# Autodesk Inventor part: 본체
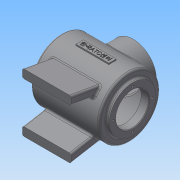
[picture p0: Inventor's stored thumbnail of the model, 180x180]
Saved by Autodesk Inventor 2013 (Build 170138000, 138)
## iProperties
Created: 2015-01
Part Number: 본체
Material: 일반
Document SubType Name: Modeling
Designer: Administrator
Density: 1 g/cm^3
Mass: 376.8 g
Surface Area: 1060.37 cm^2
Volume: 376.8 cm^3
Author: Administrator
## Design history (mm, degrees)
sketch "스케치1"
  geometry: L1 (-56, 50)-(56, 50); L2 (56, 50)-(56, 0); L3 (56, 0)-(-56, 0); L4 (-56, 0)-(-56, 50); 2 further points
  constraints: 8 end point, 2 perpendicular, 1 coincident, 1 horizontal, 1 midpoint, 1 parallel
  dimensions: "d0" = 112 distance of L1.start L1.end; "d2" = 100 diameter of L1 L3
revolve "회전1" sketch "스케치1" stored, may be unused: angle "d3" = 90 deg
sketch "스케치2"
  geometry: C1 r 50 at (0, 0) reference; C2 r 38 at (0, 0)
  constraints: 1 centre point, 1 coincident
  dimensions: "d4" = 76 diameter of C2
extrude "돌출1" join sketch "스케치2" distance "d5" = 5; taper "d6" = 0 deg
node "작업 평면1"
sketch "스케치3"
  geometry: C1 r 38 at (0, 0); 1 further point
  constraints: 1 centre point, 1 coincident
  dimensions: "d8" = 76 diameter of C1
extrude "돌출2" join sketch "스케치3" stored distance "d9" = 5; taper "d10" = 0 deg
sketch "스케치6"
  geometry: L1 (-49, 45)-(48, 45); L2 (48, 45)-(48, 0); L3 (-49, 0)-(-49, 45); L4 (-38, 62)-(38, 62) reference; L5 (-56, 50)-(56, 50) reference; L6 (-56, -50)-(56, -50) reference; L7 (56, -50)-(56, 50) reference; L8 (-56, -50)-(-56, 50) reference; L9 (-49, 0)-(48, 0); 2 further points
  constraints: 8 end point, 2 perpendicular, 1 coincident, 1 horizontal, 1 parallel, 1 point on line
  dimensions: "d12" = 5 distance between parallel lines of L1 L5; "d14" = 8 distance between parallel lines of L7 L2; "d15" = 7 distance between parallel lines of L8 L3
revolve "회전2" sketch "스케치6" stored, may be unused: angle "d16" = 90 deg
sketch "스케치8"
  geometry: C1 r 38 at (0, 0) reference; C2 r 27 at (0, 0)
  constraints: 1 centre point, 1 coincident
  dimensions: "d17" = 54 diameter of C2
extrude "돌출3" cut sketch "스케치8" stored distance "d18" = 5; taper "d19" = 0 deg
sketch "스케치9"
  geometry: C1 r 38 at (0, 0) reference; C2 r 27 at (0, 0)
  constraints: 1 centre point, 1 coincident
  dimensions: "d20" = 54 diameter of C2
extrude "돌출4" cut sketch "스케치9" stored distance "d21" = 5; taper "d22" = 0 deg
sketch "스케치10"
  geometry: C1 r 38 at (0, 0) reference; C2 r 27 at (0, 0)
  constraints: 1 centre point, 1 coincident
  dimensions: "d23" = 54 diameter of C2
extrude "돌출5" cut sketch "스케치10" stored distance "d24" = 5; taper "d25" = 0 deg
sketch "스케치11"
  geometry: C1 r 27 at (0, 0) reference; 1 further point
  constraints: 1 horizontal alignment
  dimensions: "d26" = 32 distance of point (32, 0) C1.centre
hole "구멍1" sketch "스케치11" at (32, 0) diameter "d27" = 3.242; stored, may be unused: countersink angle "d31" = 90 deg, drill point angle "d33" = 118 deg; dims "d28" = 8, "d29" = 4, "d30" = 2, "d32" = 10
sketch "스케치12"
  geometry: C1 r 27 at (0, 0) reference; 1 further point
  constraints: 1 vertical alignment
  dimensions: "d37" = 32 distance of point (0, 32) C1.centre
hole "구멍2" sketch "스케치12" at (0, 32) diameter "d38" = 3.242; stored, may be unused: countersink angle "d42" = 90 deg, drill point angle "d44" = 118 deg; dims "d39" = 8, "d40" = 4, "d41" = 2, "d43" = 10
sketch "스케치16"
  geometry: L1 (-30.865, 39.336)-(-80, 48); L2 (-80, 48)-(-80, 34); L3 (-80, 34)-(-41.901, 27.282); C1 r 27 at (0, 0) reference; C2 r 45 at (0, 0) reference; C3 r 38 at (0, 0) reference; A1 r 50 centre (0, 0) between (-30.865, 39.336) and (-41.901, 27.282) reference; 1 further point
  constraints: 6 end point, 2 point on circle, 1 parallel, 1 vertical
  dimensions: "d49" = 14 distance of L1.end L2.end; "d51" = 80 deg angle of L3 L2; "d53" = 80 distance from line of L2 point (0, 0); "d54" = 48 vertical distance of L1.end point (0, 0)
extrude "돌출6" join sketch "스케치16" stored distance "d55" = 80; taper "d56" = 0 deg
node "작업 평면5"
  node "작업 평면4"
node "작업 평면7"
  node "작업 평면6"
sketch "스케치22"
  geometry: L1 (-26, 6)-(28, 6); L2 (28, 6)-(28, -6); L3 (28, -6)-(-26, -6); L4 (-26, -6)-(-26, 6); L5 (-61, -38)-(-61, 38) reference; 1 further point
  constraints: 8 end point, 2 parallel, 1 horizontal, 1 perpendicular
  dimensions: "d66" = 54 distance of L1.start L1.end; "d68" = 12 distance of L1.end L2.end; "d69" = 6 distance from line of L1 point (0, 0); "d70" = 35 distance between parallel lines of L5 L4
extrude "돌출8" join sketch "스케치22" stored distance "d71" = 6 (= d69); taper "d72" = 0 deg
sketch "스케치23"
  geometry: L1 (-26, 6)-(28, 6) reference; L2 (-61, -38)-(-61, 38) reference; 2 further points
  constraints: 1 other
  dimensions: "d73" = 62 distance from line of L2 point (1, 0); "d74" = 6 distance from line of L1 point (1, 0)
feature "엠보싱1" sketch "스케치23" dims "d75" = 0.5, "d76" = 0
fillet "모깎기1" dims "d77" = 3
fillet "모깎기2" dims "d78" = 3
chamfer "모따기1" distance "d79" = 1; stored, may be unused: second distance "d80" = 2, angle "d81" = 45 deg
chamfer "모따기2" distance "d82" = 1; stored, may be unused: second distance "d83" = 2, angle "d84" = 45 deg
fillet "모깎기3" dims "d85" = 3
fillet "모깎기4" dims "d86" = 3
node "솔리드1"
mirror "대칭1"
pattern_circular "원형 패턴1" dims angle "d35" = 360 deg
pattern_circular "원형 패턴2" dims angle "d46" = 360 deg
mirror "대칭2"
mirror "대칭3"
node "투영된 루프1"
node "투영된 루프2"
other parameters: "d7" = 62, "d57" = -2, "d65" = 2
